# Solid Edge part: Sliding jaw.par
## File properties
Title: Sliding Jaw
Author: Deepak Maini
Template: Normal.par
Last saved by: Robert a Rhodes jr
Revision: 17
Application: Solid Edge
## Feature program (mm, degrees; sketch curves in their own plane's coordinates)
sketch used by "unnamed Protrusion 1" plane through (0, 0, 0) normal (0, -1, 0) x-axis (1, 0, 0)
  line (-34.0632, 44.45) -> (-34.0632, 0)
  line (-34.0632, 0) -> (5.6116, 0)
  line (5.6116, 0) -> (5.6116, 19.9608)
  line (-34.0632, 44.45) -> (-19.6102, 44.45)
  arc centre (-37.2382, 14.3002) radius 34.925 from (-19.6102, 44.45) to (-3.8245, 24.463) cw
  arc centre (2.2507, 26.3108) radius 6.35 from (-3.8245, 24.463) to (2.2507, 19.9608) ccw
  line (5.6116, 19.9608) -> (2.2507, 19.9608)
  dimension (linear) = 37.2382
extrude "unnamed Protrusion 1" add finite 69.7992 symmetric
sketch for "unnamed Protrusion 2" plane through (5.6116, 0, 9.9804) normal (1, 0, 0) x-axis (0, 1, 0)
extrude "unnamed Protrusion 2" add finite 65.0748 along -normal
sketch for "unnamed Cutout 1" plane through (-26.9258, -15.24, -27.8638) normal (0, -1, 0) x-axis (1, 0, 0)
extrude "unnamed Cutout 1" cut through along -normal
sketch for "unnamed Protrusion 3" plane through (5.6116, 0, -9.0696) normal (1, 0, 0) x-axis (0, 1, 0)
  arc centre (0, 26.5956) radius 23.9515 from (-23.8274, 29.0304) to (23.8274, 29.0304) cw
  line (-23.8274, 29.0304) -> (23.8274, 29.0304)
extrude "unnamed Protrusion 3" add through along -normal
sketch for "unnamed Hole 1" plane through (5.6116, 0, -0.1583) normal (1, 0, 0) x-axis (0, 1, 0)
hole "unnamed Hole 1" through
fillet "unnamed Round 1"
sketch for "unnamed Hole 2" plane through (-26.9258, 0, -38.1) normal (0, 0, -1) x-axis (0, 1, 0)
  hole centre (7.9375, 2.3876) bore radius 2.7686
hole "unnamed Hole 2" finite
sketch for "unnamed Hole 3" plane through (-26.9258, 0, -38.1) normal (0, 0, -1) x-axis (0, 1, 0)
  hole centre (-7.9375, 2.3876) bore radius 2.7686
hole "unnamed Hole 3" finite
sketch for "unnamed Hole 4" plane through (-34.0632, 0, 22.225) normal (-1, 0, 0) x-axis (0, -1, 0)
  hole centre (19.0754, 3.175) bore radius 3.175
hole "unnamed Hole 4" finite
sketch for "unnamed Hole 5" plane through (-34.0632, 0, 22.225) normal (-1, 0, 0) x-axis (0, -1, 0)
  hole centre (-19.0246, 3.175) bore radius 3.175
  dimension (linear) = 19.0246
hole "unnamed Hole 5" finite
pattern "unnamed Pattern 1" of "unnamed Hole 2", "unnamed Hole 3"
pattern "unnamed Pattern 2" of "unnamed Hole 4", "unnamed Hole 5"
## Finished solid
Body 1: solid body, 48 faces, 109 edges, 62 vertices.
  Faces by surface: plane 26, cylinder 16, torus 4, sphere 2
  Edges by curve: line 69, circle 33, intersection 7
Bounding box of the edges (mm; curved faces can reach further): 65.075 x 69.799 x 82.550, from (-59.4632, -34.8996, -38.1) to (5.6116, 34.8996, 44.45).
Cylindrical faces by radius (mm): R2.7686 x2, R3.1242 x1, R3.175 x8, R6.35 x2, R9.525 x1, R23.9515 x1, R34.925 x1
Toroidal faces (ring radius, tube radius in mm): R9.525 r3.175 x2, R31.75 r3.175 x2
Spherical faces by radius (mm): R3.175 x2
Planar faces by outward normal: +x 1, +y 4, +z 6, -x 3, -y 4, -z 7, oblique 1
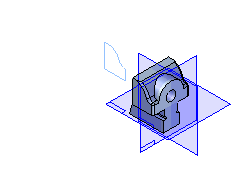
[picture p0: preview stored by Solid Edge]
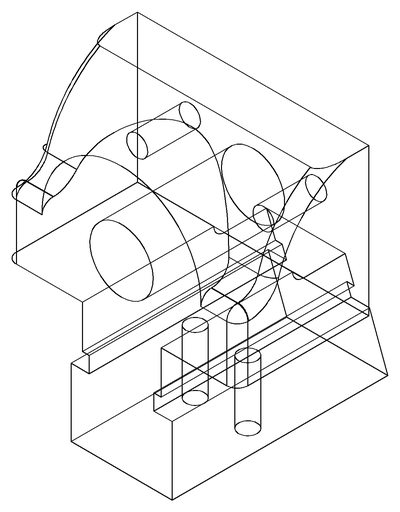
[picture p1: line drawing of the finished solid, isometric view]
